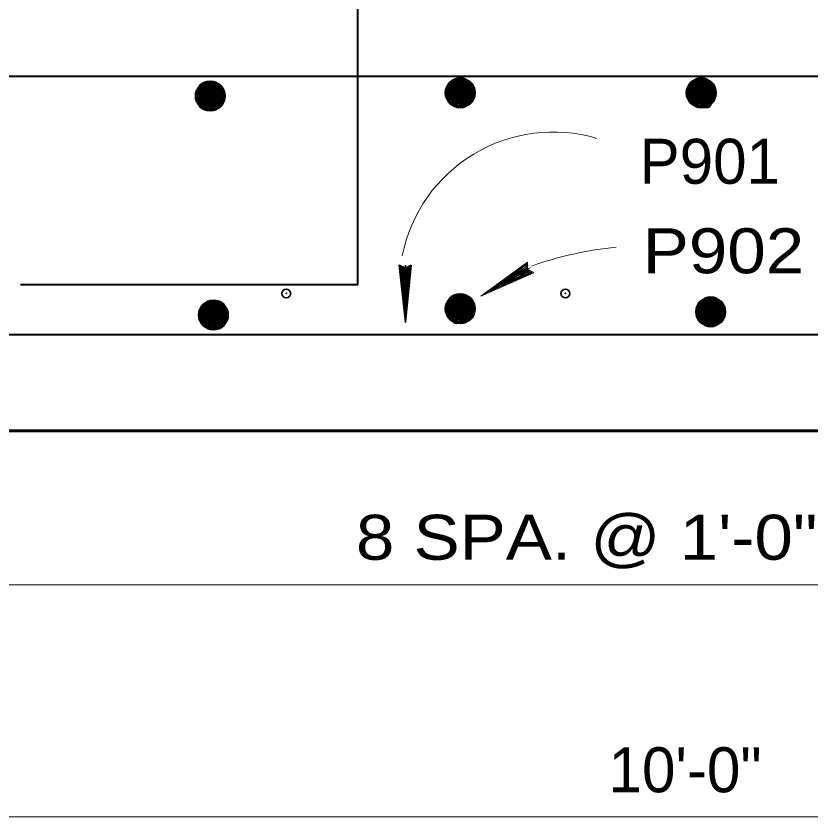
# Model space of a CAD drawing. Extents: x 4.49 to 7.69, y 0.28 to 2.27.
# Drawn here: x 6.4715 to 6.6189, y 1.8007 to 1.9491 of the extents above; entities that cross this region are included whole.
import ezdxf

# ---------------------------------------------------------------- set-up
doc = ezdxf.new("R2010")
doc.units = 0
doc.header["$LTSCALE"] = 0.0033
doc.header["$PDMODE"] = 32
doc.header["$PDSIZE"] = 0.00165
doc.layers.add('1', color=7, linetype='Continuous', lineweight=35)

msp = doc.modelspace()

# ---------------------------------------------------------------- linework, layer by layer
at = {"layer": '1', "lineweight": 40}
for p, q in [((6.367167, 1.937917), (6.831833, 1.937917)), ((6.554083, 1.935917), (6.555417, 1.936917)), ((6.556167, 1.936083), (6.554917, 1.93725)), ((6.59875, 1.935917), (6.600083, 1.936917)), ((6.600833, 1.936083), (6.599583, 1.93725)), ((6.505417, 1.935833), (6.51, 1.933667)), ((6.505667, 1.935417), (6.509583, 1.934667)), ((6.50575, 1.935833), (6.509667, 1.935167)), ((6.50575, 1.935667), (6.509667, 1.934917)), ((6.505833, 1.936167), (6.509667, 1.9355)), ((6.50775, 1.935333), (6.509083, 1.936333)), ((6.509833, 1.9355), (6.508583, 1.936667)), ((6.55175, 1.936417), (6.556333, 1.93425)), ((6.551917, 1.935417), (6.55575, 1.93475)), ((6.552, 1.936), (6.555917, 1.93525)), ((6.552, 1.935833), (6.555917, 1.935083)), ((6.552, 1.935583), (6.555833, 1.934833)), ((6.552083, 1.936417), (6.556, 1.93575)), ((6.552083, 1.93625), (6.556, 1.9355)), ((6.552167, 1.93675), (6.556, 1.936083)), ((6.596417, 1.936417), (6.601, 1.93425)), ((6.596583, 1.935417), (6.600417, 1.93475)), ((6.596667, 1.936), (6.600583, 1.93525)), ((6.596667, 1.935833), (6.600583, 1.935083)), ((6.596667, 1.935583), (6.6005, 1.934833)), ((6.59675, 1.936417), (6.600667, 1.93575)), ((6.59675, 1.93625), (6.600667, 1.9355)), ((6.596833, 1.93675), (6.600667, 1.936083)), ((6.505417, 1.934), (6.509333, 1.93325)), ((6.5055, 1.934417), (6.509333, 1.933667)), ((6.5055, 1.93425), (6.509333, 1.9335)), ((6.505583, 1.934833), (6.509417, 1.934167)), ((6.505583, 1.934667), (6.509417, 1.933917)), ((6.505667, 1.93525), (6.509583, 1.9345)), ((6.505667, 1.935), (6.5095, 1.93425)), ((6.551667, 1.934167), (6.555583, 1.933417)), ((6.551667, 1.934), (6.5555, 1.93325)), ((6.55175, 1.934583), (6.555667, 1.933833)), ((6.551833, 1.935), (6.555667, 1.93425)), ((6.551833, 1.934833), (6.555667, 1.934083)), ((6.551917, 1.93525), (6.55575, 1.9345)), ((6.596333, 1.934167), (6.60025, 1.933417)), ((6.596333, 1.934), (6.600167, 1.93325)), ((6.596417, 1.934583), (6.600333, 1.933833)), ((6.5965, 1.935), (6.600333, 1.93425)), ((6.5965, 1.934833), (6.600333, 1.934083)), ((6.596583, 1.93525), (6.600417, 1.9345)), ((6.50525, 1.933083), (6.509083, 1.932333)), ((6.50525, 1.932917), (6.509083, 1.932167)), ((6.505333, 1.933583), (6.50925, 1.932833)), ((6.505333, 1.933417), (6.509167, 1.932667)), ((6.505333, 1.933167), (6.509167, 1.9325)), ((6.509583, 1.932667), (6.505833, 1.93225)), ((6.551583, 1.933667), (6.555417, 1.932917)), ((6.551583, 1.9335), (6.555417, 1.93275)), ((6.551667, 1.93375), (6.5555, 1.933083)), ((6.555917, 1.93325), (6.552167, 1.932833)), ((6.59625, 1.933667), (6.600083, 1.932917)), ((6.59625, 1.9335), (6.600083, 1.93275)), ((6.596333, 1.93375), (6.600167, 1.933083)), ((6.600583, 1.93325), (6.596833, 1.932833)), ((6.554083, 1.895917), (6.555417, 1.896917)), ((6.556167, 1.896083), (6.554917, 1.89725)), ((6.506417, 1.895583), (6.51025, 1.894917)), ((6.508333, 1.89475), (6.509667, 1.89575)), ((6.510417, 1.894917), (6.509167, 1.896083)), ((6.55175, 1.896417), (6.556333, 1.89425)), ((6.551917, 1.895417), (6.55575, 1.89475)), ((6.552, 1.896), (6.555917, 1.89525)), ((6.552, 1.895833), (6.555917, 1.895083)), ((6.552, 1.895583), (6.555833, 1.894833)), ((6.552083, 1.896417), (6.556, 1.89575)), ((6.552083, 1.89625), (6.556, 1.8955)), ((6.552167, 1.89675), (6.556, 1.896083)), ((6.598167, 1.895833), (6.60275, 1.893667)), ((6.598417, 1.895417), (6.602333, 1.894667)), ((6.5985, 1.895833), (6.602417, 1.895167)), ((6.5985, 1.895667), (6.602417, 1.894917)), ((6.598583, 1.896167), (6.602417, 1.8955)), ((6.6005, 1.895333), (6.601833, 1.896333)), ((6.602583, 1.8955), (6.601333, 1.896667)), ((6.506, 1.89525), (6.510583, 1.893083)), ((6.506083, 1.893833), (6.509917, 1.893083)), ((6.506167, 1.89425), (6.51, 1.893583)), ((6.506167, 1.894083), (6.51, 1.893333)), ((6.50625, 1.894833), (6.510167, 1.894083)), ((6.50625, 1.894667), (6.510167, 1.893917)), ((6.50625, 1.894417), (6.510083, 1.893667)), ((6.506333, 1.89525), (6.51025, 1.894583)), ((6.506333, 1.895083), (6.51025, 1.894333)), ((6.551667, 1.894167), (6.555583, 1.893417)), ((6.551667, 1.894), (6.5555, 1.89325)), ((6.55175, 1.894583), (6.555667, 1.893833)), ((6.551833, 1.895), (6.555667, 1.89425)), ((6.551833, 1.894833), (6.555667, 1.894083)), ((6.551917, 1.89525), (6.55575, 1.8945)), ((6.598167, 1.894), (6.602083, 1.89325)), ((6.59825, 1.894417), (6.602083, 1.893667)), ((6.59825, 1.89425), (6.602083, 1.8935)), ((6.598333, 1.894833), (6.602167, 1.894167)), ((6.598333, 1.894667), (6.602167, 1.893917)), ((6.598417, 1.89525), (6.602333, 1.8945)), ((6.598417, 1.895), (6.60225, 1.89425)), ((6.505833, 1.8925), (6.509667, 1.89175)), ((6.505833, 1.892333), (6.509667, 1.891583)), ((6.505917, 1.893), (6.509833, 1.89225)), ((6.505917, 1.892833), (6.50975, 1.892083)), ((6.505917, 1.892583), (6.50975, 1.891917)), ((6.506, 1.893417), (6.509917, 1.892667)), ((6.506083, 1.893667), (6.509917, 1.892917)), ((6.551583, 1.893667), (6.555417, 1.892917)), ((6.551583, 1.8935), (6.555417, 1.89275)), ((6.551667, 1.89375), (6.5555, 1.893083)), ((6.555917, 1.89325), (6.552167, 1.892833)), ((6.598, 1.893083), (6.601833, 1.892333)), ((6.598, 1.892917), (6.601833, 1.892167)), ((6.598083, 1.893583), (6.602, 1.892833)), ((6.598083, 1.893417), (6.601917, 1.892667)), ((6.598083, 1.893167), (6.601917, 1.8925)), ((6.602333, 1.892667), (6.598583, 1.89225)), ((6.510167, 1.892083), (6.506417, 1.891667)), ((6.367583, 1.890083), (6.831667, 1.890083))]:
    msp.add_line(p, q, dxfattribs=at)
at = {"layer": '1', "lineweight": 60}
for p, q in [((6.505667, 1.935833), (6.5055, 1.932917)), ((6.505917, 1.935833), (6.505667, 1.932917)), ((6.506083, 1.935833), (6.505917, 1.932833)), ((6.50625, 1.935833), (6.506, 1.932833)), ((6.506417, 1.935833), (6.50625, 1.932833)), ((6.506667, 1.935833), (6.5065, 1.932833)), ((6.506917, 1.935833), (6.506667, 1.932833)), ((6.507, 1.93575), (6.506833, 1.932833)), ((6.507167, 1.93575), (6.507, 1.932833)), ((6.507333, 1.93575), (6.507167, 1.932833)), ((6.507583, 1.93575), (6.507333, 1.932833)), ((6.50775, 1.93575), (6.507583, 1.932833)), ((6.508, 1.935667), (6.50775, 1.93275)), ((6.50825, 1.935667), (6.508, 1.93275)), ((6.508417, 1.935667), (6.50825, 1.93275)), ((6.5085, 1.935667), (6.508333, 1.93275)), ((6.508667, 1.935667), (6.5085, 1.93275)), ((6.50875, 1.935667), (6.508583, 1.93275)), ((6.509, 1.935583), (6.50875, 1.932667)), ((6.509167, 1.935583), (6.509, 1.932667)), ((6.509333, 1.935583), (6.509083, 1.932667)), ((6.5095, 1.935583), (6.509333, 1.932667)), ((6.50975, 1.935583), (6.509583, 1.932667)), ((6.51, 1.933667), (6.509833, 1.9355)), ((6.552, 1.936417), (6.551833, 1.9335)), ((6.55225, 1.936417), (6.552, 1.9335)), ((6.552417, 1.936417), (6.55225, 1.933417)), ((6.552583, 1.936417), (6.552333, 1.933417)), ((6.55275, 1.936417), (6.552583, 1.933417)), ((6.553, 1.936417), (6.552833, 1.933417)), ((6.55325, 1.936417), (6.553, 1.933417)), ((6.553333, 1.936333), (6.553167, 1.933417)), ((6.5535, 1.936333), (6.553333, 1.933417)), ((6.553667, 1.936333), (6.5535, 1.933417)), ((6.553917, 1.936333), (6.553667, 1.933417)), ((6.554083, 1.936333), (6.553917, 1.933417)), ((6.554333, 1.93625), (6.554083, 1.933333)), ((6.554583, 1.93625), (6.554333, 1.933333)), ((6.55475, 1.93625), (6.554583, 1.933333)), ((6.554833, 1.93625), (6.554667, 1.933333)), ((6.555, 1.93625), (6.554833, 1.933333)), ((6.555083, 1.93625), (6.554917, 1.933333)), ((6.555333, 1.936167), (6.555083, 1.93325)), ((6.5555, 1.936167), (6.555333, 1.93325)), ((6.555667, 1.936167), (6.555417, 1.93325)), ((6.555833, 1.936167), (6.555667, 1.93325)), ((6.556083, 1.936167), (6.555917, 1.93325)), ((6.556333, 1.93425), (6.556167, 1.936083)), ((6.596667, 1.936417), (6.5965, 1.9335)), ((6.596917, 1.936417), (6.596667, 1.9335)), ((6.597083, 1.936417), (6.596917, 1.933417)), ((6.59725, 1.936417), (6.597, 1.933417)), ((6.597417, 1.936417), (6.59725, 1.933417)), ((6.597667, 1.936417), (6.5975, 1.933417)), ((6.597917, 1.936417), (6.597667, 1.933417)), ((6.598, 1.936333), (6.597833, 1.933417)), ((6.598167, 1.936333), (6.598, 1.933417)), ((6.598333, 1.936333), (6.598167, 1.933417)), ((6.598583, 1.936333), (6.598333, 1.933417)), ((6.59875, 1.936333), (6.598583, 1.933417)), ((6.599, 1.93625), (6.59875, 1.933333)), ((6.59925, 1.93625), (6.599, 1.933333)), ((6.599417, 1.93625), (6.59925, 1.933333)), ((6.5995, 1.93625), (6.599333, 1.933333)), ((6.599667, 1.93625), (6.5995, 1.933333)), ((6.59975, 1.93625), (6.599583, 1.933333)), ((6.6, 1.936167), (6.59975, 1.93325)), ((6.600167, 1.936167), (6.6, 1.93325)), ((6.600333, 1.936167), (6.600083, 1.93325)), ((6.6005, 1.936167), (6.600333, 1.93325)), ((6.60075, 1.936167), (6.600583, 1.93325)), ((6.601, 1.93425), (6.600833, 1.936083)), ((6.556333, 1.93425), (6.551583, 1.9335)), ((6.601, 1.93425), (6.59625, 1.9335)), ((6.51, 1.933667), (6.50525, 1.932917)), ((6.552, 1.896417), (6.551833, 1.8935)), ((6.55225, 1.896417), (6.552, 1.8935)), ((6.552417, 1.896417), (6.55225, 1.893417)), ((6.552583, 1.896417), (6.552333, 1.893417)), ((6.55275, 1.896417), (6.552583, 1.893417)), ((6.553, 1.896417), (6.552833, 1.893417)), ((6.55325, 1.896417), (6.553, 1.893417)), ((6.553333, 1.896333), (6.553167, 1.893417)), ((6.5535, 1.896333), (6.553333, 1.893417)), ((6.553667, 1.896333), (6.5535, 1.893417)), ((6.553917, 1.896333), (6.553667, 1.893417)), ((6.554083, 1.896333), (6.553917, 1.893417)), ((6.554333, 1.89625), (6.554083, 1.893333)), ((6.554583, 1.89625), (6.554333, 1.893333)), ((6.55475, 1.89625), (6.554583, 1.893333)), ((6.554833, 1.89625), (6.554667, 1.893333)), ((6.555, 1.89625), (6.554833, 1.893333)), ((6.555083, 1.89625), (6.554917, 1.893333)), ((6.555333, 1.896167), (6.555083, 1.89325)), ((6.5555, 1.896167), (6.555333, 1.89325)), ((6.555667, 1.896167), (6.555417, 1.89325)), ((6.555833, 1.896167), (6.555667, 1.89325)), ((6.556083, 1.896167), (6.555917, 1.89325)), ((6.556333, 1.89425), (6.556167, 1.896083)), ((6.598417, 1.895833), (6.59825, 1.892917)), ((6.598667, 1.895833), (6.598417, 1.892917)), ((6.598833, 1.895833), (6.598667, 1.892833)), ((6.599, 1.895833), (6.59875, 1.892833)), ((6.599167, 1.895833), (6.599, 1.892833)), ((6.599417, 1.895833), (6.59925, 1.892833)), ((6.599667, 1.895833), (6.599417, 1.892833)), ((6.59975, 1.89575), (6.599583, 1.892833)), ((6.599917, 1.89575), (6.59975, 1.892833)), ((6.600083, 1.89575), (6.599917, 1.892833)), ((6.600333, 1.89575), (6.600083, 1.892833)), ((6.6005, 1.89575), (6.600333, 1.892833)), ((6.60075, 1.895667), (6.6005, 1.89275)), ((6.601, 1.895667), (6.60075, 1.89275)), ((6.601167, 1.895667), (6.601, 1.89275)), ((6.60125, 1.895667), (6.601083, 1.89275)), ((6.601417, 1.895667), (6.60125, 1.89275)), ((6.6015, 1.895667), (6.601333, 1.89275)), ((6.60175, 1.895583), (6.6015, 1.892667)), ((6.601917, 1.895583), (6.60175, 1.892667)), ((6.602083, 1.895583), (6.601833, 1.892667)), ((6.60225, 1.895583), (6.602083, 1.892667)), ((6.6025, 1.895583), (6.602333, 1.892667)), ((6.60275, 1.893667), (6.602583, 1.8955)), ((6.50625, 1.89525), (6.506083, 1.892333)), ((6.5065, 1.89525), (6.50625, 1.892333)), ((6.506667, 1.89525), (6.5065, 1.89225)), ((6.506833, 1.89525), (6.506583, 1.89225)), ((6.507, 1.89525), (6.506833, 1.89225)), ((6.50725, 1.89525), (6.507083, 1.89225)), ((6.5075, 1.89525), (6.50725, 1.89225)), ((6.507583, 1.895167), (6.507417, 1.89225)), ((6.50775, 1.895167), (6.507583, 1.89225)), ((6.507917, 1.895167), (6.50775, 1.89225)), ((6.508167, 1.895167), (6.507917, 1.89225)), ((6.508333, 1.895167), (6.508167, 1.89225)), ((6.508583, 1.895083), (6.508333, 1.892167)), ((6.508833, 1.895083), (6.508583, 1.892167)), ((6.509, 1.895083), (6.508833, 1.892167)), ((6.509083, 1.895083), (6.508917, 1.892167)), ((6.50925, 1.895083), (6.509083, 1.892167)), ((6.509333, 1.895083), (6.509167, 1.892167)), ((6.509583, 1.895), (6.509333, 1.892083)), ((6.50975, 1.895), (6.509583, 1.892083)), ((6.509917, 1.895), (6.509667, 1.892083)), ((6.510083, 1.895), (6.509917, 1.892083)), ((6.510333, 1.895), (6.510167, 1.892083)), ((6.510583, 1.893083), (6.510417, 1.894917)), ((6.556333, 1.89425), (6.551583, 1.8935)), ((6.510583, 1.893083), (6.505833, 1.892333)), ((6.60275, 1.893667), (6.598, 1.892917))]:
    msp.add_line(p, q, dxfattribs=at)
at = {"layer": '1'}
for p, q in [((6.543, 1.90275), (6.54375, 1.895417)), ((6.543667, 1.902917), (6.543667, 1.892333)), ((6.542583, 1.902667), (6.543417, 1.895333)), ((6.54275, 1.902667), (6.5435, 1.895333)), ((6.542833, 1.902667), (6.543667, 1.895333)), ((6.5445, 1.902667), (6.5435, 1.894833)), ((6.5445, 1.902667), (6.543667, 1.894833)), ((6.544667, 1.902667), (6.54375, 1.894833)), ((6.544667, 1.902667), (6.54375, 1.894833)), ((6.544583, 1.902667), (6.54375, 1.894833))]:
    msp.add_line(p, q, dxfattribs=at)
at = {"layer": '1', "lineweight": 13}
for p, q in [((6.566083, 1.90325), (6.560167, 1.898917)), ((6.566167, 1.903167), (6.560167, 1.898833)), ((6.566167, 1.903083), (6.560333, 1.898667)), ((6.566417, 1.902917), (6.560333, 1.898583)), ((6.566833, 1.9025), (6.557667, 1.897167)), ((6.567083, 1.901667), (6.559833, 1.898583)), ((6.567083, 1.901667), (6.559917, 1.898417)), ((6.567083, 1.901583), (6.559917, 1.898333)), ((6.567083, 1.9015), (6.559917, 1.898333)), ((6.567083, 1.9015), (6.559917, 1.898333)), ((6.367583, 1.843667), (6.831667, 1.843667)), ((6.349417, 1.800667), (6.84875, 1.800667))]:
    msp.add_line(p, q, dxfattribs=at)
at = {"layer": '1', "lineweight": 40}
for points in [[(6.472333, 1.899333), (6.534833, 1.899333), (6.534833, 2.0115)], [(6.551583, 1.9335), (6.553667, 1.93225), (6.555417, 1.93275), (6.556333, 1.93425)], [(6.59625, 1.9335), (6.598333, 1.93225), (6.600083, 1.93275), (6.601, 1.93425)], [(6.50525, 1.932917), (6.507333, 1.931667), (6.509083, 1.932167), (6.51, 1.933667)], [(6.551583, 1.8935), (6.553667, 1.89225), (6.555417, 1.89275), (6.556333, 1.89425)], [(6.505833, 1.892333), (6.507917, 1.891083), (6.509667, 1.891583), (6.510583, 1.893083)], [(6.598, 1.892917), (6.600083, 1.891667), (6.601833, 1.892167), (6.60275, 1.893667)]]:
    msp.add_lwpolyline(points, dxfattribs=at)
at = {"layer": '1', "lineweight": 60}
for points in [[(6.3495, 1.87225), (6.8495, 1.87225), (6.8495, 1.955583)], [(6.555417, 1.93275), (6.555417, 1.936917), (6.55375, 1.93225), (6.55425, 1.937417), (6.552167, 1.932833), (6.552917, 1.937333), (6.5545, 1.932333), (6.551333, 1.935667), (6.556167, 1.936083), (6.552917, 1.932417), (6.554917, 1.93725), (6.55175, 1.936417), (6.551583, 1.9335)], [(6.552167, 1.932833), (6.553667, 1.935083), (6.5515, 1.936), (6.5535, 1.937417), (6.553667, 1.935167), (6.555333, 1.932833), (6.551333, 1.935167), (6.554083, 1.935917)], [(6.554917, 1.93725), (6.553667, 1.935083), (6.555917, 1.93325)], [(6.600083, 1.93275), (6.600083, 1.936917), (6.598417, 1.93225), (6.598917, 1.937417), (6.596833, 1.932833), (6.597583, 1.937333), (6.599167, 1.932333), (6.596, 1.935667), (6.600833, 1.936083), (6.597583, 1.932417), (6.599583, 1.93725), (6.596417, 1.936417), (6.59625, 1.9335)], [(6.596833, 1.932833), (6.598333, 1.935083), (6.596167, 1.936), (6.598167, 1.937417), (6.598333, 1.935167), (6.6, 1.932833), (6.596, 1.935167), (6.59875, 1.935917)], [(6.599583, 1.93725), (6.598333, 1.935083), (6.600583, 1.93325)], [(6.504833, 1.934167), (6.51, 1.934833), (6.505417, 1.935833)], [(6.509083, 1.932167), (6.509083, 1.936333), (6.507417, 1.931667), (6.507917, 1.936833), (6.505833, 1.93225), (6.506583, 1.93675), (6.508167, 1.93175), (6.505, 1.935083), (6.509833, 1.9355), (6.506583, 1.931833), (6.508583, 1.936667), (6.505417, 1.935833), (6.50525, 1.932917)], [(6.505833, 1.93225), (6.507333, 1.9345), (6.505167, 1.935417), (6.507167, 1.936833), (6.507333, 1.934583), (6.509, 1.93225), (6.505, 1.934583), (6.50775, 1.935333)], [(6.508583, 1.936667), (6.507333, 1.9345), (6.509583, 1.932667)], [(6.551167, 1.93475), (6.556333, 1.935417), (6.55175, 1.936417)], [(6.595833, 1.93475), (6.601, 1.935417), (6.596417, 1.936417)], [(6.555417, 1.89275), (6.555417, 1.896917), (6.55375, 1.89225), (6.55425, 1.897417), (6.552167, 1.892833), (6.552917, 1.897333), (6.5545, 1.892333), (6.551333, 1.895667), (6.556167, 1.896083), (6.552917, 1.892417), (6.554917, 1.89725), (6.55175, 1.896417), (6.551583, 1.8935)], [(6.552167, 1.892833), (6.553667, 1.895083), (6.5515, 1.896), (6.5535, 1.897417), (6.553667, 1.895167), (6.555333, 1.892833), (6.551333, 1.895167), (6.554083, 1.895917)], [(6.554917, 1.89725), (6.553667, 1.895083), (6.555917, 1.89325)], [(6.601833, 1.892167), (6.601833, 1.896333), (6.600167, 1.891667), (6.600667, 1.896833), (6.598583, 1.89225), (6.599333, 1.89675), (6.600917, 1.89175), (6.59775, 1.895083), (6.602583, 1.8955), (6.599333, 1.891833), (6.601333, 1.896667), (6.598167, 1.895833), (6.598, 1.892917)], [(6.598583, 1.89225), (6.600083, 1.8945), (6.597917, 1.895417), (6.599917, 1.896833), (6.600083, 1.894583), (6.60175, 1.89225), (6.59775, 1.894583), (6.6005, 1.895333)], [(6.509667, 1.891583), (6.509667, 1.89575), (6.508, 1.891083), (6.5085, 1.89625), (6.506417, 1.891667), (6.507167, 1.896167), (6.50875, 1.891167), (6.505583, 1.8945), (6.510417, 1.894917), (6.507167, 1.89125), (6.509167, 1.896083), (6.506, 1.89525), (6.505833, 1.892333)], [(6.506417, 1.891667), (6.507917, 1.893917), (6.50575, 1.894833), (6.50775, 1.89625), (6.507917, 1.894), (6.509583, 1.891667), (6.505583, 1.894), (6.508333, 1.89475)], [(6.509167, 1.896083), (6.507917, 1.893917), (6.510167, 1.892083)], [(6.551167, 1.89475), (6.556333, 1.895417), (6.55175, 1.896417)], [(6.597583, 1.894167), (6.60275, 1.894833), (6.598167, 1.895833)], [(6.601333, 1.896667), (6.600083, 1.8945), (6.602333, 1.892667)], [(6.505417, 1.893583), (6.510583, 1.89425), (6.506, 1.89525)]]:
    msp.add_lwpolyline(points, dxfattribs=at)
at = {"layer": '1'}
for points in [[(6.54475, 1.902917), (6.543667, 1.892333), (6.5425, 1.902917), (6.543667, 1.902333)], [(6.54375, 1.902167), (6.543833, 1.8975), (6.54375, 1.8975), (6.54375, 1.898417), (6.543833, 1.902167), (6.543917, 1.899167), (6.544, 1.902333), (6.544083, 1.900083), (6.544167, 1.902333), (6.543917, 1.898833), (6.54375, 1.894167), (6.5435, 1.895083), (6.5435, 1.893833), (6.5435, 1.902167), (6.543333, 1.89975), (6.543333, 1.902333), (6.54375, 1.897), (6.543083, 1.902333)]]:
    msp.add_lwpolyline(points, close=True, dxfattribs=at)
at = {"layer": '1', "lineweight": 13}
for points in [[(6.5675, 1.9015), (6.557667, 1.897167), (6.566333, 1.9035), (6.566333, 1.902167)], [(6.56625, 1.902), (6.56225, 1.899583), (6.562167, 1.899667), (6.563, 1.900167), (6.566333, 1.901917), (6.563667, 1.900417), (6.5665, 1.901917), (6.564667, 1.900667), (6.566667, 1.90175), (6.563417, 1.900167), (6.559333, 1.898), (6.560083, 1.89875), (6.558917, 1.898083), (6.566167, 1.902167), (6.564, 1.901167), (6.56625, 1.902417), (6.56175, 1.899417), (6.566083, 1.902667)]]:
    msp.add_lwpolyline(points, close=True, dxfattribs=at)
msp.add_lwpolyline([(6.56625, 1.902), (6.567, 1.9015), (6.566583, 1.901667), (6.566333, 1.901833), (6.566167, 1.90175), (6.5665, 1.901417), (6.56625, 1.90225), (6.566167, 1.90275), (6.566083, 1.90325)], dxfattribs=at)
at = {"layer": '1'}
msp.add_lwpolyline([(6.54375, 1.902167), (6.5445, 1.902583), (6.54425, 1.902333), (6.543917, 1.902167), (6.544, 1.901917), (6.544333, 1.902083), (6.543583, 1.90225), (6.543083, 1.902417), (6.542667, 1.902667)], dxfattribs=at)
at = {"layer": '1', "lineweight": 60}
for centre in [(6.5075, 1.934267), (6.553833, 1.93485), (6.5985, 1.93485), (6.553833, 1.89485), (6.60025, 1.894267), (6.508083, 1.893683)]:
    msp.add_circle(centre, 0.00264, dxfattribs=at)
at = {"layer": '1', "lineweight": 13}
for centre, radius, start, end in [((6.57105, 1.899076), 0.02852, 73.46463, 168.69611), ((6.588959, 1.841642), 0.064905, 95.48975, 109.69691)]:
    msp.add_arc(centre, radius, start, end, dxfattribs=at)
at = {"layer": '1'}
for p in [(6.507667, 1.932917), (6.553583, 1.932917), (6.5995, 1.932917), (6.521583, 1.897667), (6.573333, 1.897667), (6.507333, 1.892917), (6.553167, 1.892917), (6.598917, 1.892917)]:
    msp.add_point(p, dxfattribs=at)

# ---------------------------------------------------------------- texts
for s, height, p in [('P901', 0.008334, (6.587083, 1.918)), ('10\'-0"', 0.008333, (6.581333, 1.80525))]:
    msp.add_text(s, height=height, dxfattribs=at).set_placement(p)
at = {"layer": '1', "width": 1.15}
for s, p in [('P902', (6.587667, 1.901417)), ('8 SPA. @ 1\'-0" C/C', (6.5345, 1.848333))]:
    msp.add_text(s, height=0.008334, dxfattribs=at).set_placement(p)

doc.saveas('drawing.dxf')
